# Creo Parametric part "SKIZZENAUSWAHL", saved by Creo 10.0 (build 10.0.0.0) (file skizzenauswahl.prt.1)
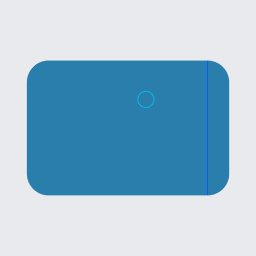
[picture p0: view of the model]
Materials in the file: S235JRG2

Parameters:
  BENENNUNG = "XXX"
  DATUM = "XX.XX.XX"
  ERSTELLER = "ARINDA"
  TEILETYP = "Fertigungsteil"
  PTC_MASTER_MATERIAL = "S235JRG2"
  SELECT_EN_NAME = "S235JRG2"
  SELECT_DIN_NAME = "RSt37-2"
  SELECT_DIN_NUMBER = "1.0038"
  SELECT_ASTM_NAME = "A 283 M Grade 2"
  MATERIAL_GROUP = "ME_ST_Baustahl"
  STANDARD_EN_DELIVERYSPEC = "DIN EN 10025"
  STANDARD_DIN_DELIVERYSPEC = "DIN 17100"

Other parameters: MASSE

Created from: KURVENAUSWAHL.PRT

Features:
  1. coordinate system
  2. datum plane "T_RECHTS_Y-Z"
  3. datum plane "T_OBEN_X-Z"
  4. datum plane "T_VORNE_X-Y"
  5. datum axis
  6. datum axis
  7. datum axis
  8. protrusion
  9. round
  10. swept cut "Ziehen 1"
  11. pattern
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
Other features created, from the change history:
  sketch "Skizze 2" (2 times)
  curve "Kurve 2"
  extrusion "Profil 2" (3 times)
  datum plane "DTM1" (3 times)
  sketch "Skizze 3" (2 times)
  sketch "Skizze 1"
  planar section "XSEC0001"
  datum curve "Kurve ID 1174"
  planar section "XSEC0002"
  datum curve "Kurve ID 1246"
  protrusion "Ziehen 2"
  extruded cut "Profil 2"
  sketch "Skizze 4"

Other named items: T_BASIC, T_X-ACHSE, T_Y-ACHSE, T_Z-ACHSE

Layers: 00_STD-ACHSEN, 00_STD-EBENEN, 00_STD-KOORDSYS, 01_EBENEN, 01_KURVEN, KURVENELEMENTE, VOLUMENGEOMETRIE

Surfaces: 33 plane, 12 cylinder, 8 cone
